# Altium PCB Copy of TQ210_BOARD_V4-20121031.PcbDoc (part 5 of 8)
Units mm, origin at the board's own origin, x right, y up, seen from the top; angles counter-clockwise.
Board outline 191.2 x 131.27 mm, 2 copper layers (TopLayer, BottomLayer); 362 components, 455 nets, 1594 pads, 630 vias.
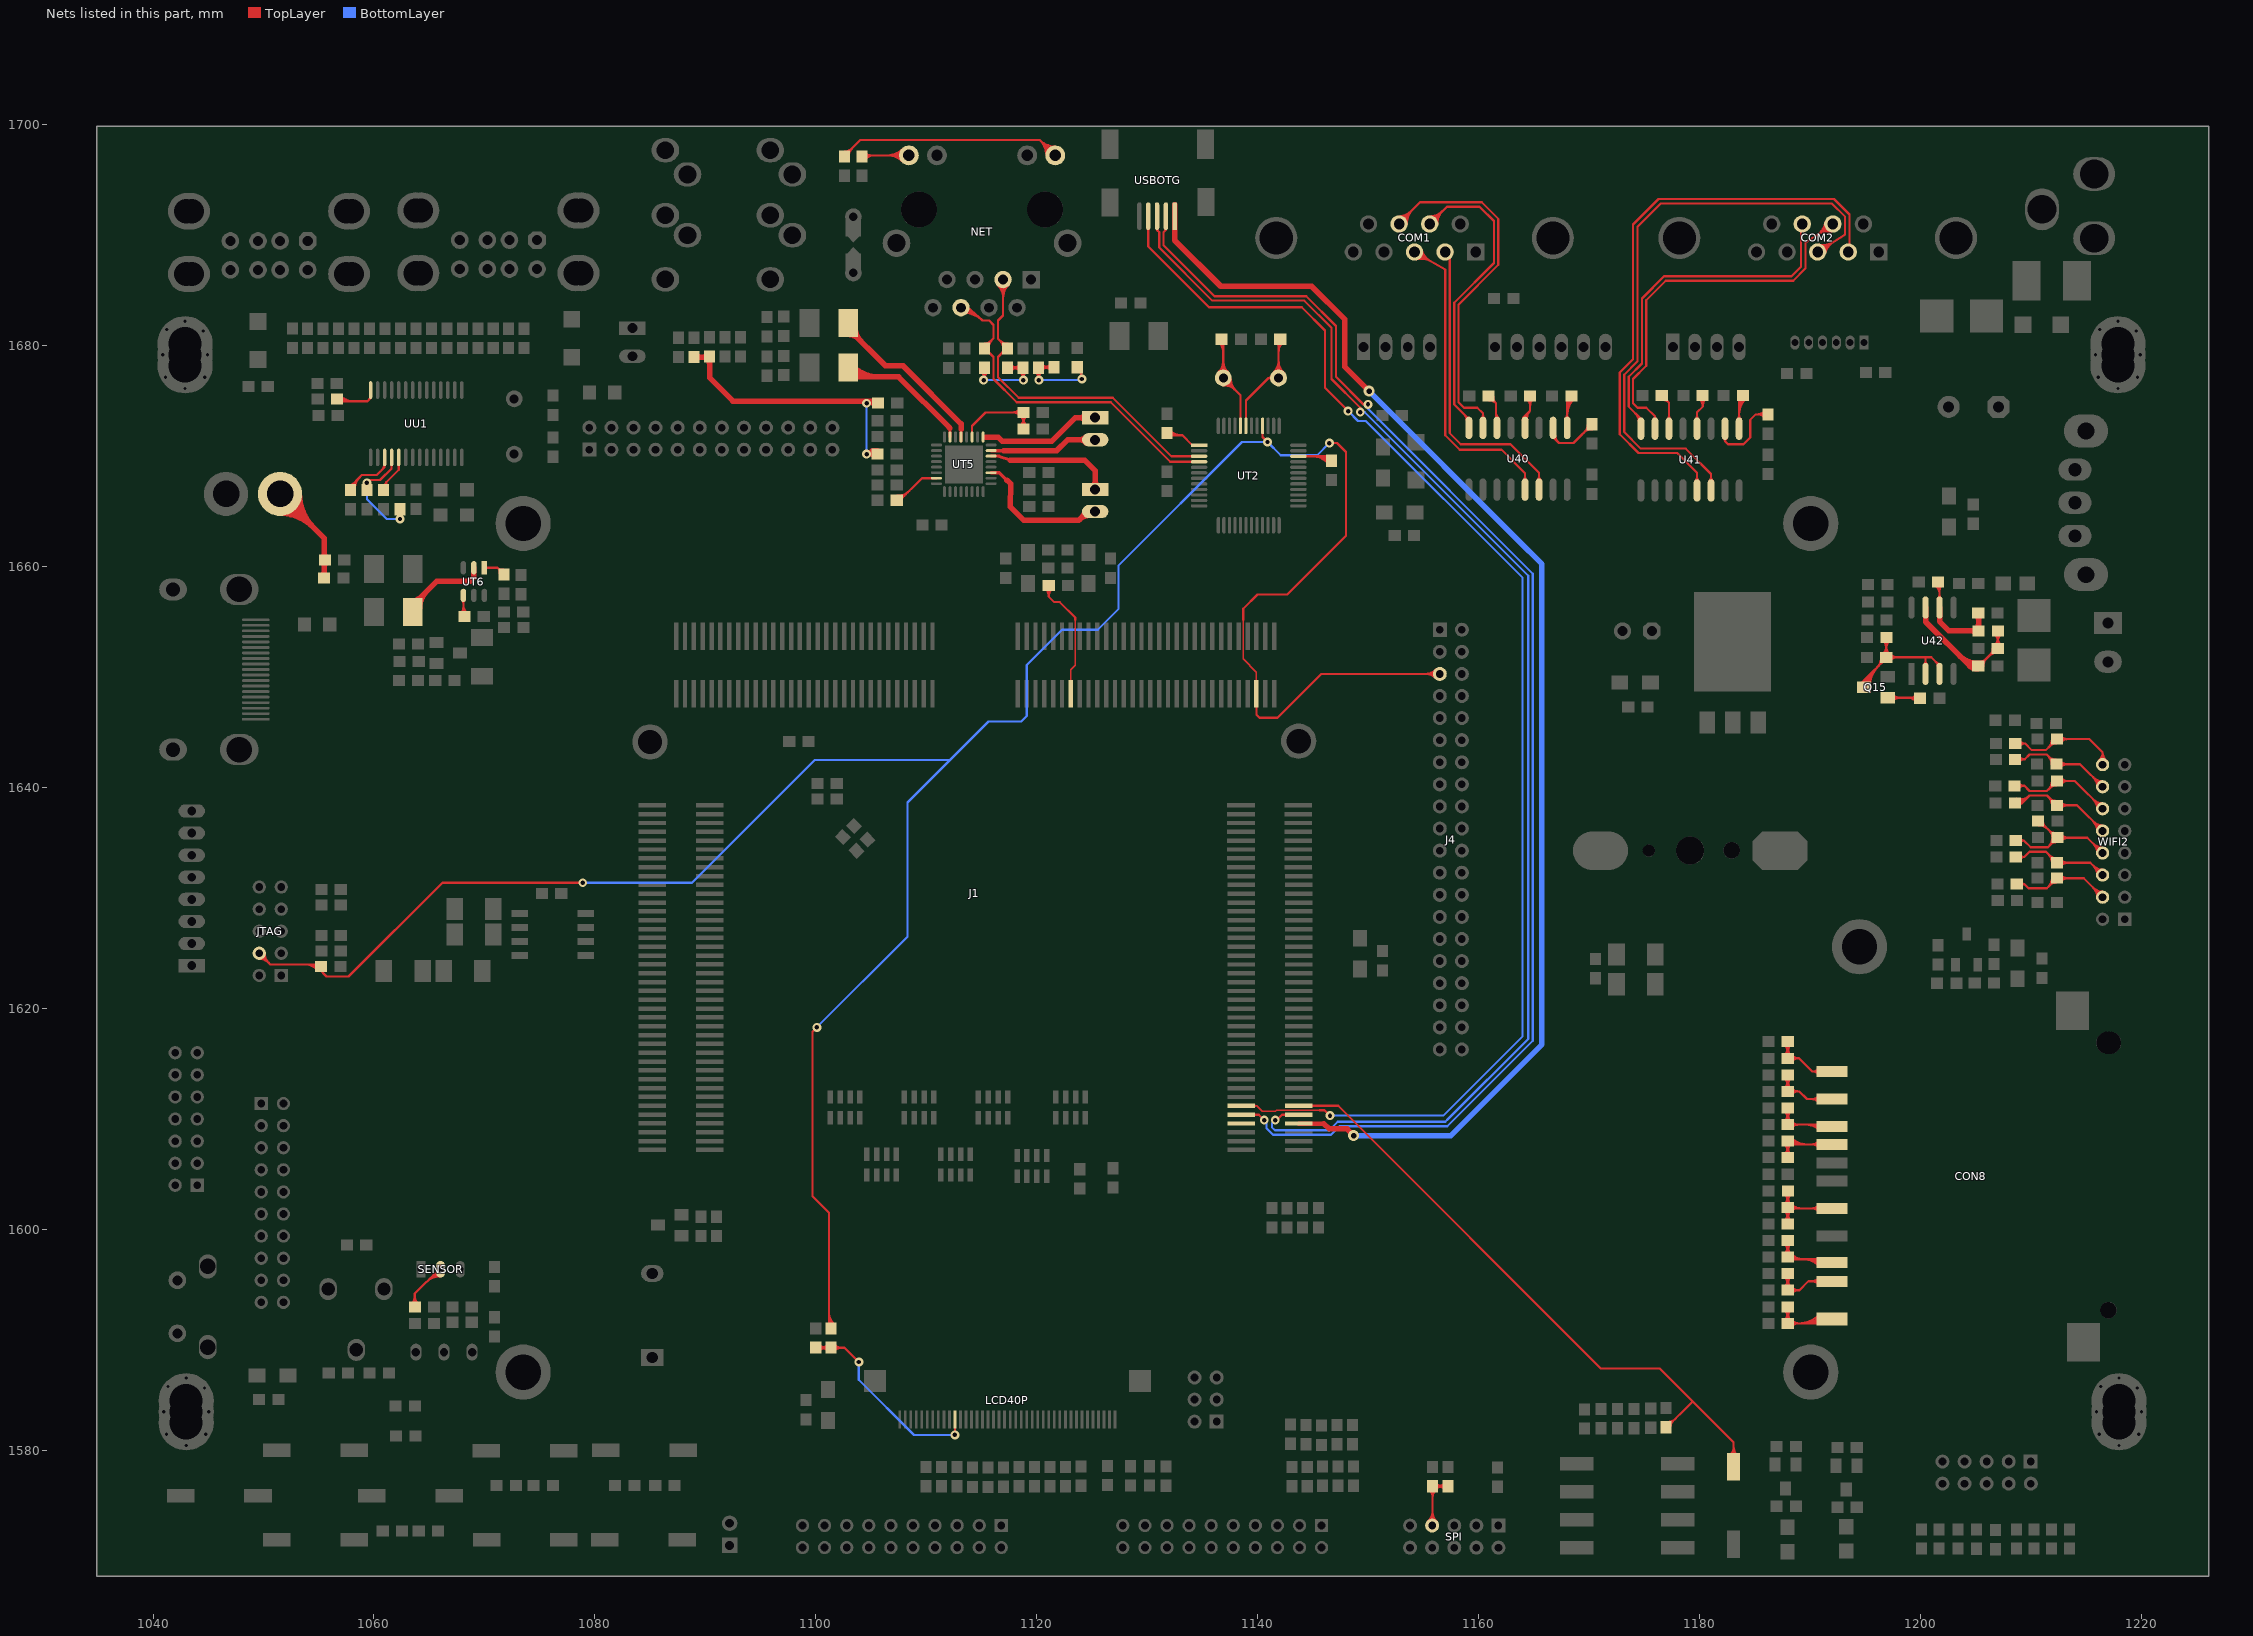
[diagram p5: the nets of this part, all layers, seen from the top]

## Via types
v1: diameter 1, hole 0.5, TopLayer to BottomLayer, 458 vias
v2: diameter 0.8, hole 0.4, TopLayer to BottomLayer, 172 vias

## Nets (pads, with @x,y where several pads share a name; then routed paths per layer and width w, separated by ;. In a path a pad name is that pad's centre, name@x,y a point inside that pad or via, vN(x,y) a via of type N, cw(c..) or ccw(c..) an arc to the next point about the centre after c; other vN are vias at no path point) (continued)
NetR31_1: LCD40P.11 R31.1 R32.1 | length 22.6
  TopLayer w0.2: R31.1@1100.2,1589.3 1102.6,1589.3 v2(1103.9,1588) ; R31.1@1100.283,1589.017 cw(c1100.966,1588.334) 1100.966,1589.3 cw(c1100.966,1590.266) R31.1@1100.283,1589.583 ; R32.1@1101.117,1589.017 ccw(c1100.434,1588.334) 1100.434,1589.3 ccw(c1100.434,1590.266) R32.1@1101.117,1589.583 ; R32.1@1101.683,1589.017 cw(c1102.366,1588.334) 1102.366,1589.3 cw(c1102.366,1590.266) R32.1@1101.683,1589.583 ; v2(1112.6,1581.4) LCD40P.11@1112.6,1582.8
  BottomLayer w0.2: v2(1103.9,1588) 1103.9,1586.4 1108.9,1581.4 v2(1112.6,1581.4)
NetR203_1: R203.1 UT2.34 | length 7.4
  TopLayer w0.2: UT2.34@1143.703,1670.004 1146.496,1670.004 R203.1@1146.5,1670 ; 1144.879,1670.004 cw(c1144.879,1667.829) R203.1@1146.417,1669.367 ; 1145.362,1670.004 cw(c1145.362,1668.312) R203.1@1146.559,1669.509 ; 1145.845,1670.004 cw(c1145.845,1668.795) R203.1@1146.7,1669.65 ; R203.1@1146.328,1670.004 cw(c1146.328,1669.278) R203.1@1146.841,1669.791
NetR206_2: CD2.1 R206.2 R207.2 | length 13.1
  TopLayer w0.2: CD2.1@1119.894,1677.682 cw(c1119.212,1676.999) 1120.177,1676.999 cw(c1121.143,1676.999) CD2.1@1120.46,1677.682 ; v2@1120.177,1676.923 CD2.1@1120.177,1678.015 ; CD2.1@1120.227,1678.065 R206.2@1121.577,1678.065 ; CD2.1@1120.46,1677.782 cw(c1121.143,1677.099) 1121.143,1678.065 cw(c1121.143,1679.031) CD2.1@1120.46,1678.348 ; R206.2@1121.294,1677.782 ccw(c1120.612,1677.099) 1120.612,1678.065 ccw(c1120.612,1679.031) R206.2@1121.294,1678.348 ; R207.2@1123.677,1678.015 cw(c1122.986,1677.17) v2@1124.072,1677.279 ; R207.2@1123.677,1678.065 1124,1678 v2(1124.1,1677)
  BottomLayer w0.2: v2(1120.2,1676.9) v2@1124.1,1676.9
NetR208_1: CD1.1 R208.1 R209.1 | length 13.2
  TopLayer w0.2: R209.1@1114.994,1677.682 cw(c1114.312,1676.999) 1115.277,1676.999 cw(c1116.243,1676.999) R209.1@1115.56,1677.682 ; v2@1115.277,1676.977 R209.1@1115.277,1678.015 ; R208.1@1117.377,1678.015 CD1.1@1118.777,1678.015 1118.777,1676.923 v2(1118.8,1676.9) ; R208.1@1117.66,1677.732 cw(c1118.343,1677.049) 1118.343,1678.015 cw(c1118.343,1678.981) R208.1@1117.66,1678.298 ; CD1.1@1118.494,1677.682 cw(c1117.812,1676.999) 1118.777,1676.999 cw(c1119.743,1676.999) CD1.1@1119.06,1677.682 ; CD1.1@1118.494,1677.732 ccw(c1117.812,1677.049) 1117.812,1678.015 ccw(c1117.812,1678.981) CD1.1@1118.494,1678.298
  BottomLayer w0.2: v2(1115.2,1676.9) v2(1118.8,1676.9)
NetR210_2: NET.9 R210.2 | length 29.3
  TopLayer w0.2: R210.2@1102.5,1697.1 1104.037,1698.637 1120.293,1698.637 NET.9@1121.68,1697.25 NET.9@1121.68,1697.847 ; R210.2@1102.6,1697.6 ccw(c1102.6,1698.566) 1103.283,1697.883 ccw(c1103.966,1697.2) R210.2@1103,1697.2 ; NET.9@1120.88,1697.25 ccw(c1118.949,1697.25) 1120.314,1698.616 ccw(c1121.68,1699.981) NET.9@1121.68,1698.05 ; NET.9@1121.08,1697.25 ccw(c1119.631,1697.25) 1120.656,1698.274 ccw(c1121.68,1699.299) NET.9@1121.68,1697.85 ; NET.9@1121.28,1697.25 ccw(c1120.314,1697.25) 1120.997,1697.933 ccw(c1121.68,1698.616) NET.9@1121.68,1697.65
NetR211_2: NET.12 R211.2 | length 12.6
  TopLayer w0.2: R211.2@1104.341,1697.059 cw(c1104.804,1696.597) 1104.804,1697.25 ; R211.2@1104.483,1696.917 cw(c1105.286,1696.114) 1105.286,1697.25 ; R211.2@1104.483,1697.483 ccw(c1105.045,1698.045) 1105.045,1697.25 ; R211.2@1104.7,1697.25 NET.12@1108.43,1697.25 ; NET.12@1107.864,1696.684 ccw(c1106.499,1695.319) 1106.499,1697.25 ccw(c1106.499,1699.181) NET.12@1107.864,1697.816 ; NET.12@1108.006,1696.826 ccw(c1106.981,1695.801) 1106.981,1697.25 ccw(c1106.981,1698.699) NET.12@1108.006,1697.674 ; NET.12@1108.147,1696.967 ccw(c1107.464,1696.284) 1107.464,1697.25 ccw(c1107.464,1698.216) NET.12@1108.147,1697.533
NetR422_1: Q15.B R422.1 | length 6.2
  TopLayer w0.2: Q15.B@1197.059,1648.135 1199.665,1648.135 R422.1@1199.7,1648.1 ; Q15.B@1197.474,1647.846 cw(c1198.171,1647.15) 1198.171,1648.135 cw(c1198.171,1649.12) Q15.B@1197.474,1648.423 ; 1198.875,1648.135 cw(c1198.875,1647.042) R422.1@1199.647,1647.815 ; 1199.054,1648.135 ccw(c1199.054,1648.974) R422.1@1199.647,1648.38 ; 1199.358,1648.135 cw(c1199.358,1647.525) R422.1@1199.789,1647.956
NetR427_1: Q15.C R421.2 R427.1 U42.2 U42.3 | length 28.7
  TopLayer w0.2: Q15.C@1194.635,1649.1 cw(c1195.444,1649.1) 1194.872,1649.672 ; Q15.C@1194.75,1649.479 ccw(c1194.663,1649.7) 1194.9,1649.7 ; Q15.C@1194.835,1649.1 cw(c1196.127,1649.1) 1195.213,1650.013 ; Q15.C@1194.9,1649.1 1194.9,1649.7 ; Q15.C@1195.035,1649.1 cw(c1196.809,1649.1) 1195.555,1650.355 ; Q15.C@1195.05,1649.479 cw(c1195.137,1649.7) 1194.9,1649.7 ; Q15.C@1195.235,1649.1 cw(c1197.492,1649.1) 1195.896,1650.696 ; Q15.C@1195.435,1649.1 cw(c1198.175,1649.1) 1196.238,1651.038 ; 1196.093,1650.893 ccw(c1195.184,1651.802) R427.1@1196.47,1651.802 ; 1196.413,1651.213 cw(c1196.87,1650.757) R427.1@1196.87,1651.402 ; 1196.435,1651.235 ccw(c1195.867,1651.802) R427.1@1196.67,1651.802 ; R427.1@1196.637,1652.085 ccw(c1195.929,1652.793) 1196.93,1652.793 ; R421.2@1196.647,1653.315 cw(c1195.965,1652.632) 1196.93,1652.632 cw(c1197.896,1652.632) R421.2@1197.213,1653.315 ; R427.1@1196.778,1651.944 ccw(c1196.412,1652.31) 1196.93,1652.31 ; 1196.93,1652.743 ccw(c1197.86,1652.743) R427.1@1197.203,1652.085 ; R421.2@1196.93,1653.598 1196.93,1651.813 R427.1@1196.92,1651.802 ; R427.1@1197.253,1651.52 cw(c1197.935,1650.837) 1197.935,1651.802 cw(c1197.935,1652.768) R427.1@1197.253,1652.085 ; U42.2@1200.355,1651.16 ccw(c1200.056,1651.458) 1200.479,1651.458 ccw(c1200.901,1651.458) U42.2@1200.602,1651.16 ; U42.2@1200.479,1650.311 1200.479,1651.781 ; 1201.437,1651.365 cw(c1201.108,1651.036) U42.3@1201.574,1651.036 ; 1201.481,1651.322 ccw(c1201.749,1651.59) U42.3@1201.749,1651.211 ; U42.3@1201.749,1650.311 1201.749,1651.054 1201,1651.802 R427.1@1196.92,1651.802 ; 1194.9,1649.7 1196.92,1651.72 R427.1@1196.92,1651.802
NetR505_2: C524.2 R504.1 R505.2 R506.1 | length 31.1
  TopLayer w0.5: R505.2@1088.981,1678.983 1090.331,1678.983 R506.1@1090.381,1679.033 1090.381,1677.119 1092.5,1675 R504.1@1105.6,1675 ; R505.2@1089.158,1678.807 cw(c1089.585,1678.38) 1089.585,1678.983 cw(c1089.585,1679.587) R505.2@1089.158,1679.16 ; R506.1@1090.204,1679.16 cw(c1089.777,1679.587) 1089.777,1678.983 cw(c1089.777,1678.38) 1090.204,1678.807 cw(c1089.777,1678.38) 1090.381,1678.38 cw(c1090.985,1678.38) R506.1@1090.558,1678.807 ; v2@1104.549,1675 cw(c1104.549,1673.796) R504.1@1105.401,1674.647 ; v2@1104.8,1670.2 1104.824,1670.224 C524.2@1105.578,1670.224 ; v2@1104.935,1670.335 cw(c1105.365,1669.905) C524.2@1105.641,1670.447 ; v2@1104.943,1670.343 cw(c1105.362,1669.923) C524.2@1105.648,1670.443 ; C524.2@1105.351,1670.047 ccw(c1104.924,1669.62) 1104.924,1670.224 ccw(c1104.924,1670.828) C524.2@1105.351,1670.401
  BottomLayer w0.2: v2(1104.6,1670.2) v2(1104.6,1674.8)
NetRA4_1: RA4.1 SENSOR.2 | length 9.3
  TopLayer w0.2: RA4.1@1063.417,1593.283 ccw(c1062.734,1593.966) 1063.7,1593.966 ccw(c1064.666,1593.966) RA4.1@1063.983,1593.283 ; RA4.1@1063.7,1593 1063.7,1594.2 1065.899,1596.399 SENSOR.2@1066.031,1596.399 ; 1064.696,1595.196 cw(c1066.031,1593.861) SENSOR.2@1066.031,1595.749 ; 1065.037,1595.537 cw(c1066.031,1594.544) SENSOR.2@1066.031,1595.949 ; 1065.379,1595.879 cw(c1066.031,1595.227) SENSOR.2@1066.031,1596.149
NetRS17_2: RS17.2 RS18.2 SPI.7 | length 12.8
  TopLayer w0.2: SPI.7@1155.433,1573.567 ccw(c1154.425,1574.575) 1155.85,1574.575 ; RS18.2@1155.567,1576.417 cw(c1154.884,1575.734) 1155.85,1575.734 cw(c1156.816,1575.734) RS18.2@1156.133,1576.417 ; SPI.7@1155.574,1573.426 ccw(c1154.908,1574.092) 1155.85,1574.092 ; SPI.7@1155.811,1573.189 1155.85,1573.228 RS18.2@1155.85,1576.75 RS17.2@1157.25,1576.75 ; 1155.85,1573.903 ccw(c1156.526,1573.903) SPI.7@1156.048,1573.426 ; 1155.85,1574.386 ccw(c1157.008,1574.386) SPI.7@1156.189,1573.567 ; RS18.2@1156.133,1576.467 cw(c1156.816,1575.784) 1156.816,1576.75 cw(c1156.816,1577.716) RS18.2@1156.133,1577.033 ; RS17.2@1156.967,1576.467 ccw(c1156.284,1575.784) 1156.284,1576.75 ccw(c1156.284,1577.716) RS17.2@1156.967,1577.033
NetRT61_1: RT61.1 UT6.1 | length 3.7
  TopLayer w0.2: UT6.1@1069.995,1659.912 1071.187,1659.912 RT61.1@1071.789,1659.31 ; UT6.1@1070.101,1659.806 cw(c1070.357,1659.55) 1070.357,1659.912 cw(c1070.357,1660.274) UT6.1@1070.101,1660.018 ; RT61.1@1071.39,1659.395 ccw(c1070.775,1659.45) 1071.212,1659.887 ccw(c1071.578,1660.253) RT61.1@1071.697,1659.749
NetRU17_1: RU17.1 UU1.14 | length 6.6
  TopLayer w0.2: RU17.1@1056.59,1674.994 1059.409,1674.994 1059.695,1675.279 UU1.14@1059.695,1676 ; RU17.1@1056.845,1675.322 ccw(c1057.639,1676.116) 1057.639,1674.994 ; RU17.1@1056.987,1674.898 cw(c1057.218,1674.667) 1057.218,1674.994 ; RU17.1@1056.987,1675.464 ccw(c1058.122,1676.598) 1058.122,1674.994 ; 1059.56,1675.144 ccw(c1059.354,1675.35) UU1.14@1059.645,1675.35
NetTVOUT_1: RT62.2 RT63.1 TVOUT.1 | length 23.5
  TopLayer w0.2: RT62.2@1055.49,1660.541 RT62.2@1055.538,1660.59
  TopLayer w0.5: TVOUT.1@1051.492,1666.59 1055.49,1662.591 RT63.1@1055.49,1658.989 ; TVOUT.1@1051.5,1664.85 cw(c1051.5,1660.671) 1054.455,1663.626 ; TVOUT.1@1051.5,1665.35 cw(c1051.5,1662.378) 1053.602,1664.479 ; TVOUT.1@1052.75,1666.6 ccw(c1055.813,1666.6) 1053.647,1664.434 ; TVOUT.1@1053.25,1666.6 ccw(c1057.52,1666.6) 1054.501,1663.58 ; RT63.1@1055.313,1659.165 ccw(c1054.886,1659.592) 1055.49,1659.592 ccw(c1056.094,1659.592) RT63.1@1055.667,1659.165 ; RT62.2@1055.333,1660.435 cw(c1054.955,1660.056) 1055.49,1660.056 ; RT62.2@1055.333,1660.788 ccw(c1054.955,1661.167) 1055.49,1661.167 ; 1055.49,1659.96 cw(c1056.162,1659.96) RT62.2@1055.687,1660.435 ; 1055.49,1661.263 ccw(c1056.162,1661.263) RT62.2@1055.687,1660.788
NetU40_1: C401.2 U40.1 | length 7.9
  TopLayer w0.2: U40.1@1167.884,1673.433 ccw(c1167.545,1673.772) 1168.024,1673.772 ; U40.1@1167.928,1672.481 1168.024,1672.577 C401.2@1168.024,1675.68 ; 1168.024,1673.681 cw(c1170.169,1673.681) C401.2@1168.652,1675.198 ; 1168.024,1673.794 ccw(c1168.534,1673.794) U40.1@1168.173,1673.433 ; 1168.024,1674.164 cw(c1169.686,1674.164) C401.2@1168.511,1675.339 ; 1168.024,1674.646 cw(c1169.203,1674.646) C401.2@1168.369,1675.48
NetU40_2: C404.1 U40.2 | length 8.7
  TopLayer w0.2: U40.2@1166.658,1671.746 U40.2@1166.658,1672.481 ; U40.2@1166.758,1672.577 1166.758,1671.742 1167.3,1671.2 1168.6,1671.2 C404.1@1170.3,1672.9 ; U40.2@1166.963,1671.866 ccw(c1167.758,1671.866) 1167.196,1671.304 ; 1169.532,1672.132 cw(c1170.3,1671.364) C404.1@1170.3,1672.45 ; 1169.653,1672.253 ccw(c1169.055,1672.85) C404.1@1169.9,1672.85 ; C404.1@1169.873,1672.473 cw(c1170.3,1672.046) C404.1@1170.3,1672.65
NetU40_4: C402.1 U40.4 | length 6.6
  TopLayer w0.2: U40.4@1164.026,1673.253 cw(c1164.396,1673.321) 1164.13,1673.587 ; U40.4@1164.118,1672.481 1164.118,1673.575 1164.669,1674.126 ; U40.4@1164.223,1673.289 cw(c1164.851,1673.405) 1164.4,1673.856 ; C402.1@1164.386,1675.198 cw(c1163.704,1674.515) 1164.669,1674.515 cw(c1165.635,1674.515) C402.1@1164.952,1675.198 ; U40.4@1164.42,1673.326 cw(c1165.307,1673.488) 1164.669,1674.126 ; C402.1@1164.669,1675.48 1164.669,1674.126
NetU40_6: C405.1 U40.6 | length 5.2
  TopLayer w0.2: C405.1@1160.919,1675.48 1161.578,1674.821 U40.6@1161.578,1672.481 ; C405.1@1160.975,1675.08 cw(c1160.988,1674.281) 1161.553,1674.846 cw(c1162.027,1675.32) C405.1@1161.365,1675.42 ; 1161.578,1674.024 ccw(c1162.414,1674.024) U40.6@1161.823,1673.433
NetU41_1: C411.2 U41.1 | length 7
  TopLayer w0.2: U41.1@1183.455,1673.356 ccw(c1183.106,1673.706) 1183.6,1673.706 ccw(c1184.094,1673.706) U41.1@1183.745,1673.356 ; U41.1@1183.6,1672.7 1183.6,1675.3 C411.2@1183.65,1675.35 ; 1183.6,1673.81 cw(c1185.59,1673.81) C411.2@1184.183,1675.217 ; 1183.6,1674.293 cw(c1185.107,1674.293) C411.2@1184.041,1675.359 ; 1183.6,1674.776 cw(c1184.624,1674.776) C411.2@1183.9,1675.5
NetU41_2: C414.1 U41.2 | length 9.5
  TopLayer w0.2: U41.2@1182.204,1671.627 cw(c1182.004,1671.37) 1182.33,1671.37 ; U41.2@1182.33,1672.7 1182.33,1671.37 ; U41.2@1182.456,1671.627 ccw(c1182.656,1671.37) 1182.33,1671.37 ; C414.1@1185.917,1673.517 ccw(c1185.234,1672.834) 1185.234,1673.8 ccw(c1185.234,1674.766) C414.1@1185.917,1674.083 ; C414.1@1186.2,1673.8 1185.1,1673.8 1184.6,1673.3 1184.6,1671.7 1184,1671.1 1182.6,1671.1 1182.33,1671.37
NetU41_4: C412.1 U41.4 | length 5.5
  TopLayer w0.2: U41.4@1179.645,1673.356 ccw(c1179.296,1673.706) 1179.79,1673.706 ccw(c1180.284,1673.706) U41.4@1179.935,1673.356 ; U41.4@1179.79,1672.5 1179.79,1673.99 1180.3,1674.5 C412.1@1180.3,1675.5 ; C412.1@1180.017,1675.217 cw(c1179.334,1674.534) 1180.3,1674.534 cw(c1181.266,1674.534) C412.1@1180.583,1675.217
NetU41_6: C415.1 U41.6 | length 5.1
  TopLayer w0.2: C415.1@1176.6,1675.5 1177.25,1674.85 U41.6@1177.25,1672.7 ; C415.1@1176.661,1675.1 cw(c1176.681,1674.331) 1177.225,1674.875 cw(c1177.681,1675.331) C415.1@1177.045,1675.435 ; U41.6@1177.105,1673.356 ccw(c1176.756,1673.706) 1177.25,1673.706 ccw(c1177.744,1673.706) U41.6@1177.395,1673.356
NetU42_6: R425.1 R426.1 R429.2 U42.6 | length 14.7
  TopLayer w0.2: R425.1@1201.387,1658.32 cw(c1200.514,1657.446) 1201.749,1657.446 ; R425.1@1201.528,1658.461 cw(c1200.997,1657.929) 1201.749,1657.929 ; U42.6@1201.625,1657.16 ccw(c1201.326,1657.458) 1201.749,1657.458 ccw(c1202.171,1657.458) U42.6@1201.872,1657.16 ; U42.6@1201.749,1656.311 1201.749,1658.549 R425.1@1201.8,1658.6 ; 1201.749,1657.827 cw(c1202.445,1657.827) R425.1@1201.953,1658.32
  TopLayer w0.5: U42.6@1201.749,1656.311 1201.749,1655.051 1202.602,1654.198 R426.1@1205.28,1654.198 1205.28,1655.77 R429.2@1205.25,1655.8 ; R426.1@1205.053,1654.021 ccw(c1204.627,1653.594) 1204.627,1654.198 ccw(c1204.627,1654.801) R426.1@1205.053,1654.374 ; R426.1@1205.103,1654.374 ccw(c1204.677,1654.801) 1205.28,1654.801 ccw(c1205.884,1654.801) R426.1@1205.457,1654.374 ; R429.2@1205.123,1655.623 cw(c1204.744,1655.244) 1205.28,1655.244 ; 1205.28,1655.149 cw(c1205.951,1655.149) R429.2@1205.477,1655.623
NetU42_7: R424.1 R426.2 R428.2 U42.7 | length 21.9
  TopLayer w0.2: R428.2@1205.3,1651.4 ccw(c1205.3,1652.366) 1205.983,1651.683 ccw(c1206.666,1651) R428.2@1205.7,1651 ; R428.2@1205.5,1651.2 1207.03,1652.73 R426.2@1207.03,1654.198 ; 1206.172,1651.872 cw(c1206.97,1651.074) R424.1@1206.97,1652.202 ; 1206.335,1652.035 ccw(c1205.767,1652.602) R424.1@1206.57,1652.602 ; R424.1@1206.513,1652.213 cw(c1206.97,1651.757) R424.1@1206.97,1652.402 ; R424.1@1206.737,1652.885 ccw(c1206.029,1653.593) 1207.03,1653.593 ; R426.2@1206.747,1653.915 cw(c1206.065,1653.232) 1207.03,1653.232 cw(c1207.996,1653.232) R426.2@1207.313,1653.915 ; R424.1@1206.878,1652.744 ccw(c1206.512,1653.11) 1207.03,1653.11 ; 1207.03,1653.543 ccw(c1207.96,1653.543) R424.1@1207.303,1652.885
  TopLayer w0.5: U42.7@1200.479,1656.311 1200.479,1655.021 1204.5,1651 R428.2@1205.25,1651 ; 1203.578,1651.922 ccw(c1205.2,1653.543) R428.2@1205.2,1651.25 ; 1204.432,1651.068 ccw(c1205.2,1651.836) R428.2@1205.2,1650.75 ; R428.2@1205.023,1650.823 ccw(c1204.596,1650.396) 1204.596,1651 ccw(c1204.596,1651.604) R428.2@1205.023,1651.177
NetUT2_1: R204.1 UT2.1 | length 5.5
  TopLayer w0.2: R204.1@1131.9,1671.9 1133.2,1671.9 1134.096,1671.004 UT2.1@1134.703,1671.004 ; R204.1@1131.941,1672.191 ccw(c1132.645,1672.895) 1132.645,1671.9 ; R204.1@1132.083,1671.767 cw(c1132.404,1671.446) 1132.404,1671.9 ; R204.1@1132.083,1672.333 ccw(c1133.128,1673.378) 1133.128,1671.9
NetUT5_7: C527.1 UT5.7 | length 6.6
  TopLayer w0.2: C527.1@1107.378,1666.224 ccw(c1107.378,1667.311) 1108.146,1666.542 ; C527.1@1107.378,1666.424 ccw(c1107.378,1667.994) 1108.488,1666.884 ; C527.1@1107.525,1665.921 1109.628,1668.024 UT5.7@1110.928,1668.024 ; C527.1@1107.778,1666.024 cw(c1108.139,1666.024) 1107.884,1666.28
NetUT5_19: SPKR.2 UT5.19 | length 14.1
  TopLayer w0.3: UT5.19@1115.878,1668.524 1116.631,1668.524 1117.304,1667.851
  TopLayer w0.5: 1117.304,1667.851 1117.634,1667.521 1117.628,1665.424 1118.828,1664.224 1123.824,1664.224 1124.6,1665 1125.299,1665 SPKR.2@1125.302,1664.998 ; 1123.927,1664.327 cw(c1124.702,1663.552) SPKR.2@1124.702,1664.648 ; 1124.178,1664.578 ccw(c1123.757,1664.998) SPKR.2@1124.352,1664.998
NetUT5_22: SPKR.1 UT5.22 | length 13.2
  TopLayer w0.3: UT5.22@1115.878,1670.024 1116.6,1670 1117.609,1669.655
  TopLayer w0.5: 1117.609,1669.655 1124.345,1669.655 1125.302,1668.698 SPKR.1@1125.302,1666.998 SPKR.1@1125.057,1666.998 ; SPKR.1@1125.054,1667.245 ccw(c1124.457,1667.843) 1125.302,1667.843 ccw(c1126.147,1667.843) SPKR.1@1125.549,1667.245
NetUT5_23: SPKL.2 UT5.23 | length 11.2
  TopLayer w0.3: UT5.23@1115.884,1670.518 1117.024,1670.518
  TopLayer w0.5: 1117.024,1670.518 1121.818,1670.518 1122.798,1671.498 SPKL.2@1125.302,1671.498 ; SPKL.2@1124.454,1671.25 ccw(c1123.857,1670.653) 1123.857,1671.498 ccw(c1123.857,1672.343) SPKL.2@1124.454,1671.745
NetUT5_25: SPKL.1 UT5.25 | length 13.6
  TopLayer w0.2: UT5.25@1115.153,1671.749 1116.505,1671.749
  TopLayer w0.5: 1115.387,1671.749 1116.505,1671.749 1116.897,1671.356 1121.356,1671.356 1123.498,1673.498 SPKL.1@1125.302,1673.498 ; SPKL.1@1124.454,1673.25 ccw(c1123.857,1672.653) 1123.857,1673.498 ccw(c1123.857,1674.343) SPKL.1@1124.454,1673.745
NetUT5_27: C510.1 C512.1 UT5.27 | length 12.2
  TopLayer w0.2: UT5.27@1114.153,1671.749 1114.153,1672.752 1115.374,1673.973 C510.1@1118.808,1673.973 C512.1@1118.808,1672.473 ; C510.1@1118.475,1673.69 ccw(c1117.792,1673.008) 1117.792,1673.973 ccw(c1117.792,1674.939) C510.1@1118.475,1674.256 ; C512.1@1118.525,1672.756 ccw(c1117.842,1673.439) 1118.808,1673.439 ccw(c1119.773,1673.439) C512.1@1119.091,1672.756 ; C510.1@1118.525,1673.69 cw(c1117.842,1673.008) 1118.808,1673.008 cw(c1119.773,1673.008) C510.1@1119.091,1673.69
NetUT5_29: C516.1 UT5.29 | length 18.2
  TopLayer w0.2: UT5.29@1113.153,1671.418 UT5.29@1113.164,1671.407
  TopLayer w0.3: UT5.29@1113.153,1671.418 1113.153,1672.459
  TopLayer w0.5: C516.1@1102.939,1681.034 cw(c1102.939,1679.763) 1103.838,1680.662 ; C516.1@1102.939,1682.054 1102.939,1681.561 1106.3,1678.2 1107.9,1678.2 1113.153,1672.947 1113.153,1672.459 ; C516.1@1103.578,1681.673 ccw(c1105.391,1681.673) 1104.109,1680.391
NetUT5_31: C515.1 UT5.31 | length 15.9
  TopLayer w0.2: 1112.148,1672.398 1112.153,1672.393
  TopLayer w0.3: UT5.31@1112.153,1671.749 1112.153,1672.393
  TopLayer w0.5: C515.1@1102.9,1677.3 1103,1677.3 1103.1,1677.2 1107.5,1677.2 1112.1,1672.6 1112.148,1672.552 ; C515.1@1103.037,1677.772 ccw(c1104.417,1679.152) 1104.417,1677.2 ; C515.1@1103.391,1678.125 ccw(c1105.624,1680.359) 1105.624,1677.2
NetUT6_2: CT61.1 UT6.2 | length 10
  TopLayer w0.5: CT61.1@1063.4,1656.5 1063.5,1656.5 1065.7,1658.7 1068.7,1658.7 1069.045,1659.045 UT6.2@1069.045,1659.912 ; CT61.1@1063.506,1656.928 ccw(c1063.506,1657.948) 1064.227,1657.227 ; CT61.1@1064.145,1656.289 cw(c1066.211,1656.289) 1064.75,1657.75
NetUT6_4: CT63.1 UT6.4 | length 4.4
  TopLayer w0.2: CT63.1@1067.857,1655.789 ccw(c1067.283,1656.363) 1068.095,1656.363 ; UT6.4@1067.989,1656.956 cw(c1067.732,1656.7) 1068.095,1656.7 cw(c1068.457,1656.7) UT6.4@1068.201,1656.956 ; CT63.1@1068.095,1655.601 UT6.4@1068.095,1657.412 ; 1068.095,1656.097 ccw(c1068.731,1656.097) CT63.1@1068.281,1655.647 ; 1068.095,1656.58 ccw(c1069.214,1656.58) CT63.1@1068.422,1655.789
NetUU1_17: RU18.1 UU1.17 | length 7.7
  TopLayer w0.2: RU18.1@1057.8,1667.2 1058.923,1668.323 1060.273,1668.323 1060.3,1668.35 1060.965,1669.015 UU1.17@1060.965,1669.904 ; RU18.1@1057.865,1667.408 ccw(c1057.865,1667.753) 1058.109,1667.509 ; RU18.1@1058.065,1667.008 cw(c1059.168,1667.008) 1058.388,1667.788 ; RU18.1@1058.265,1667.008 cw(c1059.851,1667.008) 1058.73,1668.13 ; 1060.711,1668.761 ccw(c1060.217,1669.254) UU1.17@1060.915,1669.254
NetUU1_18: RU20.2 RU21.1 UU1.18 | length 11
  TopLayer w0.2: RU21.1@1059.126,1667.329 ccw(c1058.77,1667.805) v2@1059.365,1667.805 ; RU21.1@1059.365,1667.043 v2@1059.365,1667.805 ; RU21.1@1059.604,1667.329 cw(c1059.96,1667.805) v2@1059.365,1667.805 ; UU1.18@1061.6,1669.904 1061.6,1668.9 1060.55,1667.85 1059.41,1667.85 v2@1059.365,1667.805
  BottomLayer w0.2: v2@1059.365,1667.805 1059.365,1666.122 1061.162,1664.326 v2(1062.356,1664.326)
  other v2: 1059.365,1667.6
NetUU1_19: RU19.1 UU1.19 | length 4.2
  TopLayer w0.2: RU19.1@1060.861,1667.408 ccw(c1060.858,1667.665) 1061.115,1667.665 ; RU19.1@1060.863,1667.208 ccw(c1060.86,1667.463) RU19.1@1061.115,1667.463 ; RU19.1@1061.115,1666.958 1061.115,1667.665 ; UU1.19@1062.235,1669.904 1062.235,1668.785 1061.115,1667.665
NetX6_1: C207.2 UT2.43 X6.1 | length 16.6
  TopLayer w0.2: UT2.43@1138.953,1672.754 1138.953,1675.053 1141,1677.1 ; X6.1@1141.268,1676.903 ccw(c1141,1676.819) 1141,1677.1 ; X6.1@1141.268,1677.297 cw(c1141,1677.381) 1141,1677.1 ; X6.1@1141.432,1677.568 ccw(c1140.302,1678.698) 1141.9,1678.698 ccw(c1143.498,1678.698) X6.1@1142.368,1677.568 ; X6.1@1141.573,1677.427 ccw(c1140.785,1678.215) 1141.9,1678.215 ccw(c1143.015,1678.215) X6.1@1142.227,1677.427 ; C207.2@1141.717,1680.317 cw(c1141.276,1679.876) 1141.9,1679.876 cw(c1142.724,1679.876) C207.2@1142.141,1680.459 ; 1141.9,1679.393 cw(c1143.207,1679.393) C207.2@1142.283,1680.317 ; C207.2@1141.9,1680.5 X6.1@1141.9,1677.1 1141,1677.1
NetX6_2: C208.2 UT2.44 X6.2 | length 19
  TopLayer w0.2: X6.2@1136.428,1677.568 ccw(c1135.298,1678.698) 1136.896,1678.698 ccw(c1138.494,1678.698) X6.2@1137.364,1677.568 ; C208.2@1136.517,1680.317 cw(c1135.602,1679.402) 1136.896,1679.402 ; X6.2@1136.57,1677.427 ccw(c1135.781,1678.215) 1136.896,1678.215 ccw(c1138.012,1678.215) X6.2@1137.223,1677.427 ; C208.2@1136.659,1680.459 cw(c1136.085,1679.885) 1136.896,1679.885 ; X6.2@1136.896,1676.438 cw(c1136.896,1674.84) 1138.026,1675.97 cw(c1139.156,1677.1) X6.2@1137.558,1677.1 ; X6.2@1136.896,1676.638 cw(c1136.896,1675.523) 1137.685,1676.311 cw(c1138.474,1677.1) X6.2@1137.358,1677.1 ; 1136.896,1679.867 cw(c1137.533,1679.867) C208.2@1137.083,1680.317 ; C208.2@1136.9,1680.4 1136.896,1680.396 X6.2@1136.896,1677.1 1138.453,1675.543 UT2.44@1138.453,1672.754
NRESET: J1.196 J4.5 JTAG.4 R32.2 R65.1 UT2.40 | length 245.2
  TopLayer w0.135: 1138.695,1655.195 1138.695,1651.663 1139.893,1650.465 J1.196@1139.896,1648.506
  TopLayer w0.2: JTAG.4@1049.612,1624.504 cw(c1049.612,1623.296) 1050.466,1624.15 cw(c1051.319,1625.004) JTAG.4@1050.112,1625.004 ; JTAG.4@1049.612,1624.704 cw(c1049.612,1623.979) 1050.124,1624.491 cw(c1050.636,1625.004) JTAG.4@1049.912,1625.004 ; JTAG.4@1049.612,1625.004 1050.616,1624 1054.6,1624 1055.004,1623.596 1055.7,1622.9 1057.7,1622.9 1066.2,1631.4 v2(1078.9,1631.4) ; 1053.717,1624 cw(c1053.717,1622.359) R65.1@1054.878,1623.519 ; 1054.2,1624 cw(c1054.2,1622.842) R65.1@1055.019,1623.661 ; R65.1@1054.683,1624 cw(c1054.683,1623.324) R65.1@1055.161,1623.802 ; v2(1100.1,1618.3) 1099.7,1617.9 1099.7,1603 1101.19,1601.51 1101.19,1591.11 R32.2@1101.3,1591 ; R32.2@1101.117,1591.383 ccw(c1100.941,1591.559) R32.2@1101.19,1591.559 ; 1101.19,1591.607 ccw(c1101.907,1591.607) R32.2@1101.4,1591.1 ; 1101.19,1592.09 ccw(c1102.39,1592.09) R32.2@1101.541,1591.241 ; 1101.19,1592.573 ccw(c1102.873,1592.573) R32.2@1101.683,1591.383 ; 1138.7,1655.2 1138.7,1656.209 1139.991,1657.5 1142.7,1657.5 1148,1662.8 1148,1670.4 1147.2,1671.2 v2(1146.5,1671.2) ; J1.196@1139.896,1648.506 1139.896,1646.604 1140.174,1646.326 1141.806,1646.326 1145.78,1650.3 J4.5@1156.5,1650.3 ; UT2.40@1140.453,1672.754 1140.453,1671.747 v2(1140.9,1671.3) ; J4.5@1156.122,1649.922 ccw(c1155.208,1649.008) 1155.208,1650.3 ccw(c1155.208,1651.592) J4.5@1156.122,1650.678 ; J4.5@1156.263,1650.063 ccw(c1155.691,1649.491) 1155.691,1650.3 ccw(c1155.691,1651.109) J4.5@1156.263,1650.537 ; R65.1@1054.673,1624 ccw(c1054.673,1624.29) 1054.878,1624.085 cw(c1054.673,1624.29) R65.1@1054.673,1624
  BottomLayer w0.2: v2(1078.9,1631.4) 1088.801,1631.4 1099.901,1642.5 1112.135,1642.5 ; v2(1100.1,1618.3) 1108.298,1626.498 1108.298,1638.662 1115.632,1645.997 1118.6,1645.997 1119.1,1646.497 1119.1,1651.1 1122.3,1654.3 1125.534,1654.3 1127.4,1656.166 1127.4,1660.1 1138.6,1671.3 v2(1140.9,1671.3) 1142.1,1670.1 1145.4,1670.1 v2(1146.5,1671.2) ; 1108.298,1642.498 1108.3,1642.5
OTG_DM: J1.272 USBOTG.2 | length 125.3
  TopLayer w0.2: 1131.591,1690.397 ccw(c1131.451,1690.537) USBOTG.2@1131.616,1690.645 ; USBOTG.2@1131.7,1691.75 1131.7,1690.506 1131.494,1690.3 1131.494,1689.1 1136.094,1684.5 1144.4,1684.5 1147.1,1681.8 1147.1,1677.2 1149.6,1674.7 v2(1150,1674.7) ; J1.272@1138.525,1610.384 1140.116,1610.384 v2(1140.6,1609.9) ; J1.272@1139.635,1610.324 cw(c1139.781,1610.178) 1139.781,1610.384 ; J1.272@1139.635,1610.465 ccw(c1139.831,1610.661) 1139.831,1610.384
  BottomLayer w0.2: v2(1140.6,1609.9) 1140.817,1609.683 1140.817,1609.165 1141.4,1608.582 1146.658,1608.582 1147.426,1609.35 1157.179,1609.35 1164.92,1617.091 1164.92,1659.38 1150,1674.3 v2(1150,1674.7)
OTG_DP: J1.271 USBOTG.3 | length 124.4
  TopLayer w0.2: USBOTG.3@1130.9,1691.75 1130.9,1690.494 ; USBOTG.3@1130.978,1690.637 ccw(c1131.115,1690.527) 1130.991,1690.403 ; v2@1141.726,1609.9 1142.21,1610.384 J1.271@1143.725,1610.384 ; v2(1149.3,1674) 1149.3,1674.4 1146.7,1677 1146.7,1681.634 1144.234,1684.1 1135.91,1684.1 1131.094,1688.916 1131.094,1690.3 1130.9,1690.494 ; 1130.9,1690.494 cw(c1131.063,1690.494) 1130.962,1690.621 ccw(c1131.063,1690.494) 1130.9,1690.494 ; 1130.9,1690.494 ccw(c1130.737,1690.494) 1130.838,1690.621 cw(c1130.737,1690.494) 1130.9,1690.494
  BottomLayer w0.2: v2@1141.383,1609.683 v2(1141.6,1609.9) 1141.298,1609.598 1141.298,1609.268 1141.578,1608.988 1146.488,1608.988 1147.25,1609.75 1157,1609.75 1157.25,1610 1164.5,1617.25 1164.5,1659.2 1149.7,1674 v2(1149.3,1674)
OTG_DRVVBUS: J1.274
OTG_ID: J1.270 USBOTG.4 | length 123.5
  TopLayer w0.135: J1.270@1138.515,1611.195 1139.905,1611.195 1140.41,1610.69 1141.618,1610.69 1141.722,1610.795 1145.605,1610.795 ; J1.270@1139.658,1611.101 cw(c1139.884,1610.875) 1139.884,1611.195 cw(c1139.884,1611.514) J1.270@1139.658,1611.288
  TopLayer w0.2: USBOTG.4@1130.029,1690.629 cw(c1129.859,1690.459) 1130.1,1690.459 cw(c1130.341,1690.459) USBOTG.4@1130.171,1690.629 ; USBOTG.4@1130.1,1691.75 1130.1,1688.995 1135.595,1683.5 1144,1683.5 1146.1,1681.4 1146.1,1676.2 v2(1148.2,1674.1) ; 1145.605,1610.795 1146.071,1610.795 v2(1146.556,1610.309)
  BottomLayer w0.2: v2(1146.556,1610.309) 1156.809,1610.309 1164,1617.5 1164,1659 1149.8,1673.2 1149.1,1673.2 v2(1148.2,1674.1) v2@1148.2,1674.2
OTG_VBUS: J1.273 USBOTG.1 | length 120.5
  TopLayer w0.2: USBOTG.1@1132.484,1692.783 USBOTG.1@1132.5,1692.767
  TopLayer w0.4: J1.273@1143.725,1609.584 1145.99,1609.584
  TopLayer w0.5: USBOTG.1@1132.5,1692.767 1132.5,1689.567 1136.667,1685.4 1144.9,1685.4 1147.9,1682.4 1147.9,1678.1 v1(1150.1,1675.9) ; 1145.99,1609.584 1146.5,1609.1 1148.1,1609.1 v1(1148.69,1608.506)
  BottomLayer w0.5: v1(1148.69,1608.506) 1157.506,1608.506 1165.75,1616.75 1165.75,1660.25 1163.558,1662.442 v1(1150.1,1675.9)
PWRHOLD: J1.154 RT2.1 | length 12.8
  TopLayer w0.135: J1.154@1123.096,1648.506 1123.096,1650.696 1123.497,1651.097 1123.497,1655.197
  TopLayer w0.2: RT2.1@1120.817,1658.017 cw(c1120.134,1657.334) 1121.1,1657.334 cw(c1122.066,1657.334) RT2.1@1121.383,1658.017 ; RT2.1@1121.1,1658.3 1121.1,1657.3 1121.6,1656.8 1122.1,1656.8 1123.497,1655.403 1123.497,1655.197
PWRON: J1.269 KEYON.1 RT1.1 | length 62.9
  TopLayer w0.2: J1.269@1143.715,1611.195 1147.305,1611.195 1171.1,1587.4 1176.434,1587.4 1183.098,1580.737 KEYON.1@1183.098,1578.502 ; RT1.1@1176.9,1582 1176.967,1582 1179.401,1584.434 ; RT1.1@1177,1582.35 ccw(c1177,1583.115) 1177.541,1582.574 ; RT1.1@1177,1582.55 ccw(c1177,1583.798) 1177.882,1582.915 ; RT1.1@1177.4,1582.15 cw(c1178.084,1582.15) 1177.6,1582.633 ; KEYON.1@1182.744,1579.506 ccw(c1181.891,1580.359) 1183.098,1580.359 ccw(c1184.305,1580.359) KEYON.1@1183.451,1579.506 ; KEYON.1@1182.886,1579.364 ccw(c1182.373,1579.877) 1183.098,1579.877 ccw(c1183.822,1579.877) KEYON.1@1183.31,1579.364
RSCTS0: COM1.7 U40.8 | length 33
  TopLayer w0.2: COM1.7@1155.584,1691.04 1157.144,1692.6 1160.1,1692.6 1161.4,1691.3 1161.4,1687.5 1157.8,1683.9 1157.8,1674.7 1159.138,1673.362 U40.8@1159.138,1672.577 ; COM1.7@1155.584,1691.527 ccw(c1155.584,1692.704) 1156.416,1691.872 ccw(c1157.249,1691.04) COM1.7@1156.072,1691.04 ; COM1.7@1155.584,1691.727 ccw(c1155.584,1693.387) 1156.758,1692.213 ccw(c1157.931,1691.04) COM1.7@1156.272,1691.04 ; 1158.737,1673.763 cw(c1158.263,1673.289) U40.8@1158.934,1673.289 ; 1158.913,1673.587 ccw(c1159.138,1673.812) U40.8@1159.138,1673.493
RSCTS1: COM2.8 U41.8 | length 33.3
  TopLayer w0.2: 1174.234,1673.866 cw(c1173.579,1673.211) U41.8@1174.505,1673.211 ; 1174.575,1673.525 cw(c1174.262,1673.211) U41.8@1174.705,1673.211 ; U41.8@1174.71,1672.5 1174.71,1673.39 1173.6,1674.5 1173.6,1677.2 1174.8,1678.4 1174.8,1684.3 1176.8,1686.3 1188.334,1686.3 1189.2,1687.166 1189.2,1690.924 COM2.8@1189.316,1691.04
RSRTS0: COM1.8 U40.7 | length 38.5
  TopLayer w0.2: COM1.8@1152.7,1691 1154.7,1693 1160.3,1693 1161.8,1691.5 1161.8,1687.334 1158.2,1683.734 1158.2,1674.9 1158.7,1674.4 1159.9,1674.4 1160.408,1673.892 U40.7@1160.408,1672.577 ; COM1.8@1152.816,1691.527 ccw(c1152.816,1692.521) 1153.518,1691.818 ; COM1.8@1152.816,1691.727 ccw(c1152.816,1693.204) 1153.86,1692.16 ; COM1.8@1153.103,1691.04 cw(c1153.98,1691.04) 1153.36,1691.66 ; COM1.8@1153.303,1691.04 cw(c1154.663,1691.04) 1153.701,1692.001 ; COM1.8@1153.503,1691.04 cw(c1155.346,1691.04) 1154.043,1692.343 ; U40.7@1160.264,1673.433 ccw(c1159.914,1673.783) 1160.408,1673.783 ccw(c1160.903,1673.783) U40.7@1160.553,1673.433
RSRTS1: COM2.7 U41.7 | length 39.4
  TopLayer w0.2: U41.7@1175.857,1673.375 ccw(c1175.674,1673.62) 1175.98,1673.62 ; U41.7@1175.98,1672.5 1175.98,1673.62 ; U41.7@1176.103,1673.375 cw(c1176.286,1673.62) 1175.98,1673.62 ; COM2.7@1191.407,1691.159 cw(c1189.773,1691.447) 1190.725,1690.088 cw(c1191.677,1688.729) COM2.7@1191.965,1690.363 ; COM2.7@1191.604,1691.125 cw(c1190.446,1691.329) 1191.121,1690.365 cw(c1191.796,1689.401) COM2.7@1192,1690.56 ; COM2.7@1192.084,1691.04 1189.6,1689.3 1189.6,1687 1188.5,1685.9 1176.966,1685.9 1175.2,1684.134 1175.2,1678.2 1174,1677 1174,1674.8 1174.4,1674.4 1175.2,1674.4 1175.98,1673.62
RSRXD0: COM1.3 U40.13 | length 33.6
  TopLayer w0.2: COM1.3@1154.213,1688.5 1157,1686.9 1157,1671.9 1158.3,1670.6 1162.1,1670.6 1164.218,1668.482 U40.13@1164.218,1666.989 ; COM1.3@1154.34,1688.03 cw(c1154.647,1686.894) 1155.233,1687.914 cw(c1155.819,1688.935) COM1.3@1154.683,1688.627 ; COM1.3@1154.392,1687.836 cw(c1154.826,1686.235) 1155.652,1687.674 cw(c1156.478,1689.113) COM1.3@1154.876,1688.68 ; U40.13@1164.074,1667.845 ccw(c1163.724,1668.195) 1164.218,1668.195 ccw(c1164.713,1668.195) U40.13@1164.363,1667.845
RSRXD1: COM2.2 U41.13 | length 54.8
  TopLayer w0.2: U41.13@1179.645,1667.768 ccw(c1179.296,1668.118) 1179.79,1668.118 ccw(c1180.284,1668.118) U41.13@1179.935,1667.768 ; U41.13@1179.79,1666.912 1179.79,1668.51 1178,1670.3 1174.5,1670.3 1172.8,1672 1172.8,1677.6 1174,1678.8 1174,1691 1176.3,1693.3 1192.2,1693.3 1193.6,1691.9 COM2.2@1193.6,1688.5
RSTXD0: COM1.2 U40.14 | length 28.4
  TopLayer w0.2: COM1.2@1156.981,1688.5 1157.4,1688.081 1157.4,1672.1 1158.4,1671.1 1162.9,1671.1 1165.488,1668.512 U40.14@1165.488,1666.989 ; U40.14@1165.344,1667.845 ccw(c1164.994,1668.195) 1165.488,1668.195 ccw(c1165.983,1668.195) U40.14@1165.633,1667.845
RSTXD1: COM2.3 U41.14 | length 60
  TopLayer w0.2: U41.14@1180.915,1667.768 ccw(c1180.566,1668.118) 1181.06,1668.118 ccw(c1181.554,1668.118) U41.14@1181.205,1667.768 ; U41.14@1181.06,1666.912 1181.06,1668.4 1178.76,1670.7 1174.7,1670.7 1173.2,1672.2 1173.2,1677.4 1174.4,1678.6 1174.4,1690.8 1176.5,1692.9 1192,1692.9 1193.2,1691.7 1193.2,1690.1 COM2.3@1190.713,1688.5 ; COM2.3@1190.816,1688.976 ccw(c1191.066,1690.126) 1191.702,1689.137 ccw(c1192.339,1688.147) COM2.3@1191.189,1688.397 ; COM2.3@1190.859,1689.172 ccw(c1191.211,1690.794) 1192.109,1689.398 ccw(c1193.006,1688.002) COM2.3@1191.385,1688.354
RX+: NET.3 R208.2 UT2.3 | length 38
  TopLayer w0.2: NET.3@1116.474,1685.514 cw(c1115.3,1684.34) 1116.96,1684.34 cw(c1118.62,1684.34) NET.3@1117.446,1685.514 ; 1116.609,1680.533 ccw(c1117.377,1681.301) R208.2@1117.377,1680.215 ; NET.3@1116.615,1685.655 cw(c1115.783,1684.823) 1116.96,1684.823 cw(c1118.137,1684.823) NET.3@1117.305,1685.655 ; 1116.73,1680.412 cw(c1116.132,1679.815) R208.2@1116.977,1679.815 ; 1116.76,1679.26 cw(c1117.376,1678.644) R208.2@1117.377,1679.515 ; 1116.809,1679.309 ccw(c1116.403,1679.715) R208.2@1116.977,1679.715 ; R208.2@1116.95,1680.192 ccw(c1117.377,1680.619) R208.2@1117.377,1680.015 ; R208.2@1116.96,1679.46 1116.5,1679 1116.5,1677.166 1118.366,1675.3 1126.9,1675.3 1132.196,1670.004 UT2.3@1134.703,1670.004 ; NET.3@1116.96,1686 1116.96,1682.76 1116.5,1682.3 1116.5,1680.642 R208.2@1117.377,1679.765
RX-: NET.6 R209.2 UT2.4 | length 38.6
  TopLayer w0.2: NET.6@1113.141,1683.572 cw(c1113.232,1682.462) 1113.97,1683.297 ; NET.6@1113.157,1683.373 cw(c1113.286,1681.813) 1114.322,1682.987 ; NET.6@1113.174,1683.174 cw(c1113.34,1681.164) 1114.674,1682.676 ; NET.6@1113.19,1682.974 cw(c1113.393,1680.515) 1115.026,1682.365 ; NET.6@1113.4,1683.8 1115.1,1682.3 1115.7,1682.3 1116.1,1681.9 1116.1,1680.7 1115.5,1680.1 R209.2@1115.5,1679.7 ; NET.6@1113.4,1683.9 NET.6@1113.727,1683.764 ; R209.2@1115.277,1680.215 ccw(c1115.277,1681.031) 1115.854,1680.454 ; R209.2@1115.477,1679.815 cw(c1116.11,1679.815) R209.2@1115.663,1680.263 ; R209.2@1115.6,1679.7 1115.6,1679.5 1116.1,1679 1116.1,1677 1118.2,1674.9 1126.7,1674.9 1132.096,1669.504 UT2.4@1134.703,1669.504 ; R209.2@1115.677,1679.815 cw(c1116.793,1679.815) 1116.004,1680.604
SD0_CDN: CON8.11 RS8.2 RS16.1 | length 13.6
  TopLayer w0.2: RS16.1@1187.717,1606.783 ccw(c1187.034,1607.466) 1188,1607.466 ccw(c1188.966,1607.466) RS16.1@1188.283,1606.783 ; RS8.2@1187.717,1607.717 cw(c1187.034,1607.034) 1188,1607.034 cw(c1188.966,1607.034) RS8.2@1188.283,1607.717 ; RS16.1@1188,1606.5 RS8.2@1188,1608 ; RS8.2@1188,1607.693 1188.012,1607.705 CON8.11@1191.995,1607.705 ; RS8.2@1188.05,1608 ccw(c1188.762,1608.712) 1188.762,1607.705 ; RS8.2@1188.191,1608.141 ccw(c1189.245,1609.195) 1189.245,1607.705 ; RS8.2@1188.333,1608.283 ccw(c1189.728,1609.678) 1189.728,1607.705 ; CON8.11@1190.812,1607.422 ccw(c1190.129,1606.739) 1190.129,1607.705 ccw(c1190.129,1608.671) CON8.11@1190.812,1607.988
SD0_CLK: CON8.5 CS1.1 RS3.2 RS11.2 | length 17.2
  TopLayer w0.2: RS3.2@1187.717,1600.783 ccw(c1187.034,1601.466) 1188,1601.466 ccw(c1188.966,1601.466) RS3.2@1188.283,1600.783 ; RS11.2@1187.717,1601.717 cw(c1187.034,1601.034) 1188,1601.034 cw(c1188.966,1601.034) RS11.2@1188.283,1601.717 ; RS11.2@1187.717,1602.283 ccw(c1187.034,1602.966) 1188,1602.966 ccw(c1188.966,1602.966) RS11.2@1188.283,1602.283 ; CS1.1@1187.736,1603.215 cw(c1187.098,1602.577) 1188,1602.577 ; RS3.2@1188,1600.5 CS1.1@1188,1603.5 ; RS11.2@1188,1602 1188.095,1601.905 CON8.5@1191.995,1601.905 ; RS11.2@1188,1602.488 cw(c1189.029,1602.488) CS1.1@1188.301,1603.215 ; 1188,1602.971 cw(c1188.546,1602.971) CS1.1@1188.16,1603.357 ; RS11.2@1188.191,1602.141 ccw(c1188.762,1602.712) 1188.762,1601.905 ; RS11.2@1188.333,1601.717 cw(c1188.786,1601.264) 1188.786,1601.905 ; RS11.2@1188.333,1602.283 ccw(c1189.245,1603.195) 1189.245,1601.905 ; CON8.5@1190.812,1601.622 ccw(c1190.129,1600.939) 1190.129,1601.905 ccw(c1190.129,1602.871) CON8.5@1190.812,1602.188
SD0_CMD: CON8.2 RS4.2 RS12.2 | length 12.4
  TopLayer w0.2: RS4.2@1187.717,1609.783 ccw(c1187.034,1610.466) 1188,1610.466 ccw(c1188.966,1610.466) RS4.2@1188.283,1609.783 ; RS12.2@1187.717,1610.717 cw(c1187.034,1610.034) 1188,1610.034 cw(c1188.966,1610.034) RS12.2@1188.283,1610.717 ; RS12.2@1188,1611 RS4.2@1188,1609.5 1191.358,1609.5 CON8.2@1191.387,1609.471 ; RS4.2@1188.333,1609.217 cw(c1189.016,1608.534) 1189.016,1609.5 cw(c1189.016,1610.466) RS4.2@1188.333,1609.783 ; 1189.659,1609.5 cw(c1189.659,1607.868) CON8.2@1190.812,1609.022 ; 1190.141,1609.5 cw(c1190.141,1608.351) CON8.2@1190.954,1609.164 ; CON8.2@1190.6,1609.5 ccw(c1190.6,1609.8) CON8.2@1190.812,1609.588 ; CON8.2@1190.624,1609.5 cw(c1190.624,1608.834) CON8.2@1191.095,1609.305
SD0_DATA0: CON8.7 RS2.2 RS10.2 | length 15
  TopLayer w0.2: RS10.2@1187.717,1597.783 ccw(c1187.034,1598.466) 1188,1598.466 ccw(c1188.966,1598.466) RS10.2@1188.283,1597.783 ; RS2.2@1187.717,1598.717 cw(c1187.034,1598.034) 1188,1598.034 cw(c1188.966,1598.034) RS2.2@1188.283,1598.717 ; RS10.2@1188,1597.5 RS2.2@1188,1599 ; RS10.2@1188.05,1597.5 ccw(c1188.522,1597.972) RS10.2@1188.522,1597.304 ; RS10.2@1188.161,1597.304 1191.696,1597.304 CON8.7@1191.995,1597.005 ; RS10.2@1188.191,1597.641 ccw(c1189.005,1598.455) 1189.005,1597.304 ; RS10.2@1188.333,1597.217 cw(c1188.543,1597.007) RS10.2@1188.543,1597.304 ; RS10.2@1188.333,1597.783 ccw(c1189.488,1598.938) 1189.488,1597.304 ; 1189.407,1597.304 cw(c1189.407,1595.317) CON8.7@1190.812,1596.722 ; 1189.889,1597.304 cw(c1189.889,1595.799) CON8.7@1190.954,1596.864 ; 1190.372,1597.304 cw(c1190.372,1596.282) CON8.7@1191.095,1597.005
SD0_DATA1: CON8.8 RS1.2 RS9.2 | length 11.9
  TopLayer w0.2: RS1.2@1187.717,1594.783 ccw(c1187.034,1595.466) 1188,1595.466 ccw(c1188.966,1595.466) RS1.2@1188.283,1594.783 ; RS9.2@1187.717,1595.717 cw(c1187.034,1595.034) 1188,1595.034 cw(c1188.966,1595.034) RS9.2@1188.283,1595.717 ; RS9.2@1188,1596 RS1.2@1188,1594.5 1189.065,1594.5 1189.87,1595.305 CON8.8@1191.995,1595.305 ; RS1.2@1188.333,1594.217 cw(c1189.016,1593.534) 1189.016,1594.5 cw(c1189.016,1595.466) RS1.2@1188.333,1594.783 ; CON8.8@1190.812,1595.022 ccw(c1190.129,1594.339) 1190.129,1595.305 ccw(c1190.129,1596.271) CON8.8@1190.812,1595.588
SD0_DATA2: CON8.9 RS6.2 RS14.2 | length 11.9
  TopLayer w0.2: RS6.2@1187.717,1615.783 ccw(c1187.034,1616.466) 1188,1616.466 ccw(c1188.966,1616.466) RS6.2@1188.283,1615.783 ; RS14.2@1187.717,1616.717 cw(c1187.034,1616.034) 1188,1616.034 cw(c1188.966,1616.034) RS14.2@1188.283,1616.717 ; RS14.2@1188,1617 RS6.2@1188,1615.5 1189.016,1615.5 ; RS6.2@1188.333,1615.217 cw(c1189.016,1614.535) 1189.016,1615.5 ; RS6.2@1188.333,1615.783 ccw(c1189.016,1616.465) 1189.016,1615.5 ; CON8.9@1190.795,1614.041 ccw(c1190.211,1613.527) 1190.211,1614.305 ; CON8.9@1190.795,1614.569 cw(c1190.211,1615.083) 1190.211,1614.305 ; CON8.9@1191.995,1614.305 1190.211,1614.305 ; 1189.016,1615.5 1190.211,1614.305
SD0_DATA3: CON8.1 RS5.2 RS13.2 | length 11.9
  TopLayer w0.2: RS13.2@1187.717,1612.783 ccw(c1187.034,1613.466) 1188,1613.466 ccw(c1188.966,1613.466) RS13.2@1188.283,1612.783 ; RS5.2@1187.717,1613.717 cw(c1187.034,1613.034) 1188,1613.034 cw(c1188.966,1613.034) RS5.2@1188.283,1613.717 ; RS5.2@1188,1614 RS13.2@1188,1612.5 1189.044,1612.5 1189.739,1611.805 CON8.1@1191.995,1611.805 ; RS13.2@1188.333,1612.217 cw(c1189.016,1611.534) 1189.016,1612.5 cw(c1189.016,1613.466) RS13.2@1188.333,1612.783 ; CON8.1@1190.812,1611.522 ccw(c1190.129,1610.839) 1190.129,1611.805 ccw(c1190.129,1612.771) CON8.1@1190.812,1612.088
SD0_WPN: CON8.10 RS7.2 RS15.1 | length 16.2
  TopLayer w0.2: RS15.1@1187.717,1591.783 ccw(c1187.034,1592.466) 1188,1592.466 ccw(c1188.966,1592.466) RS15.1@1188.283,1591.783 ; RS7.2@1187.717,1592.717 cw(c1187.034,1592.034) 1188,1592.034 cw(c1188.966,1592.034) RS7.2@1188.283,1592.717 ; RS7.2@1188.105,1593.105 RS7.2@1188,1593 RS15.1@1188,1591.5 1191.171,1591.5 CON8.10@1191.26,1591.589 ; RS15.1@1188.333,1591.217 cw(c1189.016,1590.534) 1189.016,1591.5 cw(c1189.016,1592.466) RS15.1@1188.333,1591.783 ; 1189.01,1591.5 ccw(c1189.01,1594.09) CON8.10@1190.841,1592.259 ; 1189.493,1591.5 ccw(c1189.493,1593.607) CON8.10@1190.983,1592.117 ; 1189.976,1591.5 ccw(c1189.976,1593.124) CON8.10@1191.124,1591.976 ; 1190.459,1591.5 ccw(c1190.459,1592.641) CON8.10@1191.266,1591.834 ; CON8.10@1191.165,1591.905 CON8.10@1191.995,1591.905
SD3_CDN: RW7.2 RW15.2 WIFI2.10 | length 20.5
  TopLayer w0.2: RW7.2@1208.568,1638.412 ccw(c1208.733,1639.01) 1209.171,1638.571 ; RW7.2@1208.571,1638.605 1209.205,1638.605 ; RW7.2@1208.621,1638.605 ccw(c1208.838,1639.39) 1209.414,1638.814 ; RW7.2@1208.675,1638.798 ccw(c1208.943,1639.771) 1209.657,1639.057 ; RW7.2@1208.728,1638.991 ccw(c1209.048,1640.152) 1209.9,1639.3 ; RW7.2@1208.995,1638.461 cw(c1209.205,1638.379) 1209.205,1638.605 ; RW7.2@1208.995,1638.749 ccw(c1209.205,1638.831) 1209.205,1638.605 ; 1211.603,1639.173 cw(c1210.835,1638.405) RW15.2@1211.921,1638.405 ; 1211.724,1639.052 ccw(c1212.321,1639.65) RW15.2@1212.321,1638.805 ; RW15.2@1211.945,1638.832 cw(c1211.518,1638.405) RW15.2@1212.121,1638.405 ; RW15.2@1212.704,1638.122 cw(c1213.387,1637.439) 1213.387,1638.405 cw(c1213.387,1639.371) RW15.2@1212.704,1638.688 ; WIFI2.10@1216.012,1636.088 ccw(c1214.805,1636.088) 1215.658,1636.942 ccw(c1216.512,1637.795) WIFI2.10@1216.512,1636.588 ; WIFI2.10@1216.212,1636.088 ccw(c1215.487,1636.088) 1215.999,1636.6 ccw(c1216.512,1637.112) WIFI2.10@1216.512,1636.388 ; WIFI2.10@1216.512,1636.088 1214.195,1638.405 RW15.2@1212.371,1638.405 1211.476,1639.3 1209.9,1639.3 ; 1209.205,1638.605 1209.9,1639.3
SD3_CLK: CW4.2 RW3.2 RW11.2 WIFI2.8 | length 22.6
  TopLayer w0.2: RW3.2@1208.643,1635.219 1209.381,1635.219 1210,1634.6 1211.541,1634.6 RW11.2@1212.415,1635.474 1215.126,1635.474 WIFI2.8@1216.512,1634.088 ; RW3.2@1209.041,1635.021 cw(c1209.381,1634.828) 1209.381,1635.219 cw(c1209.381,1635.61) RW3.2@1209.041,1635.417 ; CW4.2@1210.665,1636.995 1210.805,1636.995 RW11.2@1212.1,1635.7 ; CW4.2@1210.715,1636.595 cw(c1210.715,1635.413) 1211.551,1636.249 ; CW4.2@1210.715,1636.795 cw(c1210.715,1636.096) CW4.2@1211.21,1636.59 ; CW4.2@1211.115,1636.995 ccw(c1211.865,1636.995) 1211.335,1636.465 ; 1211.616,1636.184 ccw(c1212.365,1636.933) RW11.2@1212.365,1635.874 ; 1211.646,1634.706 ccw(c1210.878,1635.474) 1211.965,1635.474 ccw(c1211.092,1635.474) 1211.709,1636.091 ; 1211.767,1634.827 cw(c1212.365,1634.229) RW11.2@1212.365,1635.074 ; RW11.2@1211.957,1635.843 ccw(c1212.365,1636.25) RW11.2@1212.365,1635.674 ; RW11.2@1211.988,1635.047 ccw(c1211.561,1635.474) RW11.2@1212.165,1635.474 ; RW11.2@1212.378,1635.511 RW11.2@1212.501,1635.388 ; RW11.2@1212.748,1635.191 cw(c1213.43,1634.508) 1213.43,1635.474 cw(c1213.43,1636.44) RW11.2@1212.748,1635.757 ; WIFI2.8@1216.012,1634.088 ccw(c1214.805,1634.088) 1215.658,1634.942 ccw(c1216.512,1635.795) WIFI2.8@1216.512,1634.588 ; WIFI2.8@1216.212,1634.088 ccw(c1215.487,1634.088) 1215.999,1634.6 ccw(c1216.512,1635.112) WIFI2.8@1216.512,1634.388
SD3_CMD: RW4.2 RW12.2 WIFI2.12 | length 17.3
  TopLayer w0.2: RW4.2@1208.543,1640.169 1209.431,1640.169 ; RW4.2@1208.904,1639.918 cw(c1209.431,1639.492) 1209.431,1640.169 ; RW4.2@1208.904,1640.42 ccw(c1209.431,1640.846) 1209.431,1640.169 ; 1211.603,1639.837 ccw(c1210.835,1640.605) RW12.2@1211.921,1640.605 ; 1211.724,1639.958 cw(c1212.321,1639.36) RW12.2@1212.321,1640.205 ; RW12.2@1211.945,1640.178 ccw(c1211.518,1640.605) RW12.2@1212.121,1640.605 ; RW12.2@1212.704,1640.322 cw(c1213.387,1639.639) 1213.387,1640.605 cw(c1213.387,1641.571) RW12.2@1212.704,1640.888 ; WIFI2.12@1216.012,1638.088 ccw(c1214.805,1638.088) 1215.658,1638.942 ccw(c1216.512,1639.795) WIFI2.12@1216.512,1638.588 ; WIFI2.12@1216.212,1638.088 ccw(c1215.487,1638.088) 1215.999,1638.6 ccw(c1216.512,1639.112) WIFI2.12@1216.512,1638.388 ; WIFI2.12@1216.512,1638.088 1213.995,1640.605 RW12.2@1212.371,1640.605 1211.466,1639.7 1209.9,1639.7 1209.431,1640.169
SD3_DATA0: RW2.2 RW10.2 WIFI2.6 | length 16.6
  TopLayer w0.2: RW2.2@1208.643,1633.719 1209.419,1633.719 ; RW2.2@1209.031,1633.505 cw(c1209.419,1633.261) 1209.419,1633.719 ; RW2.2@1209.031,1633.933 ccw(c1209.419,1634.177) 1209.419,1633.719 ; 1211.595,1633.994 cw(c1210.806,1633.205) RW10.2@1211.921,1633.205 ; 1211.745,1633.844 ccw(c1212.321,1634.421) RW10.2@1212.321,1633.605 ; RW10.2@1211.936,1633.653 cw(c1211.488,1633.205) RW10.2@1212.121,1633.205 ; RW10.2@1212.415,1633.174 1212.384,1633.205 1212.378,1633.211 1211.389,1634.2 1209.9,1634.2 1209.419,1633.719 ; RW10.2@1212.454,1633.288 RW10.2@1212.371,1633.205 1215.395,1633.205 WIFI2.6@1216.512,1632.088 ; RW10.2@1212.704,1632.922 cw(c1213.387,1632.239) 1213.387,1633.205 cw(c1213.387,1634.171) RW10.2@1212.704,1633.488 ; WIFI2.6@1216.012,1632.088 ccw(c1214.805,1632.088) 1215.658,1632.942 ccw(c1216.512,1633.795) WIFI2.6@1216.512,1632.588 ; WIFI2.6@1216.212,1632.088 ccw(c1215.487,1632.088) 1215.999,1632.6 ccw(c1216.512,1633.112) WIFI2.6@1216.512,1632.388
SD3_DATA1: RW1.2 RW9.2 WIFI2.4 | length 16.2
  TopLayer w0.2: RW1.2@1208.743,1631.269 1209.431,1631.269 ; RW1.2@1209.153,1631.095 cw(c1209.431,1630.961) 1209.431,1631.269 ; RW1.2@1209.153,1631.443 ccw(c1209.431,1631.577) 1209.431,1631.269 ; 1211.603,1631.037 ccw(c1210.835,1631.805) RW9.2@1211.921,1631.805 ; 1211.724,1631.158 cw(c1212.321,1630.56) RW9.2@1212.321,1631.405 ; RW9.2@1211.945,1631.378 ccw(c1211.518,1631.805) RW9.2@1212.121,1631.805 ; RW9.2@1212.704,1631.522 cw(c1213.387,1630.839) 1213.387,1631.805 cw(c1213.387,1632.771) RW9.2@1212.704,1632.088 ; WIFI2.4@1216.012,1630.088 ccw(c1214.805,1630.088) 1215.658,1630.942 ccw(c1216.512,1631.795) WIFI2.4@1216.512,1630.588 ; WIFI2.4@1216.212,1630.088 ccw(c1215.487,1630.088) 1215.999,1630.6 ccw(c1216.512,1631.112) WIFI2.4@1216.512,1630.388 ; WIFI2.4@1216.512,1630.088 1214.795,1631.805 RW9.2@1212.371,1631.805 1211.466,1630.9 1209.8,1630.9 1209.431,1631.269
SD3_DATA2: RW6.2 RW14.2 WIFI2.16 | length 17.5
  TopLayer w0.2: RW6.2@1208.6,1644 1209.5,1644 ; RW6.2@1208.958,1643.745 cw(c1209.5,1643.297) 1209.5,1644 ; RW6.2@1208.958,1644.255 ccw(c1209.5,1644.703) 1209.5,1644 ; 1211.603,1643.637 ccw(c1210.835,1644.405) RW14.2@1211.921,1644.405 ; 1211.724,1643.758 cw(c1212.321,1643.16) RW14.2@1212.321,1644.005 ; RW14.2@1211.945,1643.978 ccw(c1211.518,1644.405) RW14.2@1212.121,1644.405 ; RW14.2@1212.704,1644.122 cw(c1213.387,1643.439) 1213.387,1644.405 cw(c1213.387,1645.371) RW14.2@1212.704,1644.688 ; WIFI2.16@1216.183,1642.465 ccw(c1215.551,1643.188) 1216.512,1643.188 ; WIFI2.16@1216.314,1642.314 ccw(c1215.935,1642.748) 1216.512,1642.748 ccw(c1217.088,1642.748) WIFI2.16@1216.709,1642.314 ; WIFI2.16@1216.512,1642.088 1216.512,1643.188 ; WIFI2.16@1216.84,1642.465 cw(c1217.472,1643.188) 1216.512,1643.188 ; 1209.5,1644 1210.1,1643.4 1211.366,1643.4 RW14.2@1212.371,1644.405 1215.295,1644.405 1216.512,1643.188
SD3_DATA3: RW5.2 RW13.2 WIFI2.14 | length 17
  TopLayer w0.2: RW5.2@1208.593,1642.569 1209.469,1642.569 ; RW5.2@1208.957,1642.321 cw(c1209.469,1641.917) 1209.469,1642.569 ; RW5.2@1208.957,1642.817 ccw(c1209.469,1643.221) 1209.469,1642.569 ; 1211.566,1642.895 cw(c1210.798,1642.127) RW13.2@1211.885,1642.127 ; 1211.687,1642.775 ccw(c1212.285,1643.372) RW13.2@1212.285,1642.527 ; RW13.2@1211.908,1642.554 cw(c1211.481,1642.127) RW13.2@1212.085,1642.127 ; RW13.2@1212.668,1641.844 cw(c1213.35,1641.162) 1213.35,1642.127 cw(c1213.35,1643.093) RW13.2@1212.668,1642.41 ; WIFI2.14@1216.012,1640.088 ccw(c1214.805,1640.088) 1215.658,1640.942 ccw(c1216.512,1641.795) WIFI2.14@1216.512,1640.588 ; WIFI2.14@1216.212,1640.088 ccw(c1215.487,1640.088) 1215.999,1640.6 ccw(c1216.512,1641.112) WIFI2.14@1216.512,1640.388 ; WIFI2.14@1216.512,1640.088 1214.472,1642.127 RW13.2@1212.335,1642.127 1211.462,1643 1209.9,1643 1209.469,1642.569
